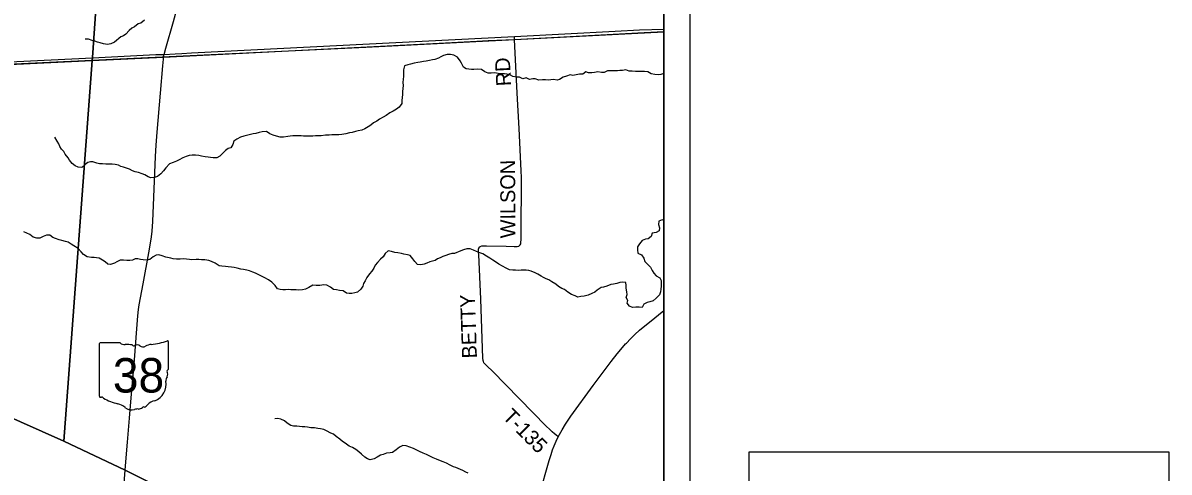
# Model space of a CAD drawing. Extents: x 0 to 36.5, y 0 to 25.3.
# Drawn here: x 6.451 to 10.831, y 15.88 to 17.597 of the extents above; entities that cross this region are included whole.
import ezdxf

# ---------------------------------------------------------------- set-up
doc = ezdxf.new("R2010")
doc.units = 0
for name, color, linetype in [('DV_X_Township_Line', 7, 'Continuous'), ('GM_X_Minor_River', 7, 'Continuous'), ('GM_X_Rail_Line', 7, 'Continuous'), ('GM_X_State_Location', 7, 'Continuous'), ('GM_X_State_Route', 7, 'Continuous'), ('GM_X_State_Shield', 7, 'Continuous'), ('GM_X_Township_Road', 7, 'Continuous'), ('GM_X_Township_Road_Text', 7, 'Continuous'), ('GM_X_US_Route', 7, 'Continuous'), ('SH_Cut_Line', 7, 'Continuous'), ('SH_Data', 7, 'Continuous'), ('SH_Text', 7, 'Continuous')]:
    doc.layers.add(name, color=color, linetype=linetype)

msp = doc.modelspace()

# ---------------------------------------------------------------- linework, layer by layer
at = {"layer": 'DV_X_Township_Line'}
msp.add_lwpolyline([(5.1383, 16.6527), (6.6079, 15.9978), (6.7158, 17.4536), (6.7165, 17.4645), (6.7464, 17.8914), (6.7478, 17.9113), (6.7968, 18.6079), (6.9145, 19.9406), (6.9868, 20.9), (6.1845, 20.9)], dxfattribs=at)
for points in [[(8.9, 14.8674), (8.9, 20.9), (6.9868, 20.9), (6.9145, 19.9406), (6.7968, 18.6079), (6.7478, 17.9113), (6.7464, 17.8914), (6.7165, 17.4645), (6.7158, 17.4536), (6.6079, 15.9978), (6.8419, 15.8878), (7.703, 15.458), (7.7552, 15.432), (7.7814, 15.4189), (7.8139, 15.4027), (8.0723, 15.2737), (8.5228, 15.0526)], [(2.1, 16.2788), (2.1, 14.1), (8.9, 14.1), (8.9, 14.8674), (8.5228, 15.0526), (8.0723, 15.2737), (7.8139, 15.4027), (7.7814, 15.4189), (7.7552, 15.432), (7.703, 15.458), (6.8419, 15.8878), (6.6079, 15.9978), (5.1383, 16.6527), (4.8891, 16.7511), (4.0938, 16.595), (2.4938, 16.3413), (2.1039, 16.2931)]]:
    msp.add_lwpolyline(points, close=True, dxfattribs=at)
at = {"layer": 'GM_X_Minor_River'}
for points in [[(6.9151, 17.6076), (6.9013, 17.5966), (6.8915, 17.5929), (6.877, 17.5815), (6.8671, 17.577), (6.8568, 17.5675), (6.845, 17.5546), (6.8355, 17.5478), (6.8252, 17.5444), (6.8016, 17.5239), (6.7872, 17.5167), (6.7738, 17.5141), (6.759, 17.5168), (6.7458, 17.5207), (6.7363, 17.5233), (6.7253, 17.5268), (6.7158, 17.5302), (6.7021, 17.5345), (6.6884, 17.5349)], [(8.9, 17.404), (8.8887, 17.4), (8.8781, 17.3989), (8.8655, 17.3994), (8.8522, 17.4026), (8.839, 17.4099), (8.8269, 17.4112), (8.8158, 17.4109), (8.8026, 17.411), (8.7919, 17.4115), (8.7794, 17.412), (8.7676, 17.4121), (8.7547, 17.4171), (8.7422, 17.4157), (8.7327, 17.4146), (8.7232, 17.414), (8.7099, 17.4133), (8.6977, 17.4134), (8.6852, 17.4139), (8.6718, 17.4076), (8.6623, 17.4077), (8.6483, 17.4101), (8.635, 17.4079), (8.6251, 17.4061), (8.6118, 17.4058), (8.6019, 17.4097), (8.5905, 17.4014), (8.5775, 17.4012), (8.565, 17.3983), (8.552, 17.3961), (8.5422, 17.3981), (8.5285, 17.3936), (8.5151, 17.3899), (8.5018, 17.3813), (8.4922, 17.378), (8.4786, 17.3804), (8.4683, 17.3801), (8.458, 17.3783), (8.4486, 17.3799), (8.4368, 17.3789), (8.4227, 17.3778), (8.4091, 17.3833), (8.3996, 17.3837), (8.387, 17.3808), (8.3745, 17.3874), (8.3608, 17.3837), (8.3487, 17.3891), (8.3366, 17.3892), (8.3237, 17.3916), (8.3138, 17.3967), (8.3006, 17.4006), (8.2911, 17.4029), (8.2763, 17.4027), (8.2668, 17.4039), (8.2539, 17.4059), (8.2402, 17.4053), (8.2288, 17.405), (8.2159, 17.4097), (8.2031, 17.4186), (8.1883, 17.4206), (8.1746, 17.4192), (8.1647, 17.4193), (8.1552, 17.4197), (8.1454, 17.4217), (8.1344, 17.4279), (8.1266, 17.4428), (8.1221, 17.4523), (8.112, 17.4657), (8.098, 17.4738), (8.0847, 17.4762), (8.0718, 17.4764), (8.0588, 17.4723), (8.0485, 17.4678), (8.039, 17.4618), (8.0256, 17.4574), (8.0157, 17.4556), (8.0043, 17.453), (7.9925, 17.4504), (7.9815, 17.449), (7.9697, 17.4476), (7.9602, 17.4462), (7.9457, 17.4433), (7.932, 17.4396), (7.9225, 17.4374), (7.9091, 17.4326), (7.9056, 17.4181), (7.9059, 17.4063), (7.9054, 17.3923), (7.9037, 17.3817), (7.9033, 17.3695), (7.9035, 17.3577), (7.9031, 17.3467)], [(7.9031, 17.3467), (7.9022, 17.3345), (7.9017, 17.3231), (7.8992, 17.3011), (7.8987, 17.2889), (7.8883, 17.2746), (7.8788, 17.2678), (7.8662, 17.26), (7.8532, 17.2529), (7.8398, 17.2435), (7.8272, 17.2367), (7.8138, 17.2296), (7.8035, 17.2221), (7.7909, 17.2154), (7.7802, 17.206), (7.7707, 17.2004), (7.7577, 17.1921), (7.7466, 17.1877), (7.7317, 17.184), (7.7218, 17.1814), (7.7097, 17.1785), (7.699, 17.1767), (7.6845, 17.173), (7.6697, 17.1708), (7.6587, 17.1698), (7.6458, 17.1692), (7.6317, 17.1693), (7.6214, 17.1686), (7.607, 17.168), (7.5903, 17.1658), (7.5804, 17.1652), (7.5693, 17.1649), (7.5591, 17.1646), (7.5439, 17.1647), (7.534, 17.1648), (7.5238, 17.1645), (7.5139, 17.165), (7.5021, 17.1655), (7.4926, 17.1652), (7.4823, 17.1649), (7.4728, 17.1638), (7.4629, 17.1624), (7.4466, 17.1603), (7.434, 17.1604), (7.42, 17.1647), (7.4071, 17.1675), (7.3947, 17.1733), (7.3814, 17.1821), (7.3651, 17.1804), (7.3544, 17.1782), (7.3411, 17.1749), (7.3312, 17.1731), (7.3202, 17.1709), (7.295, 17.1643), (7.2824, 17.1598), (7.2687, 17.1527), (7.2576, 17.1448), (7.2537, 17.1323), (7.2452, 17.1202), (7.2357, 17.1165), (7.2258, 17.1098), (7.2031, 17.0875), (7.1917, 17.0808), (7.178, 17.0813), (7.1682, 17.0829), (7.1587, 17.0845), (7.148, 17.0857), (7.1332, 17.0874), (7.1234, 17.0897), (7.1101, 17.0914), (7.0976, 17.0911), (7.0869, 17.0901), (7.0751, 17.0867), (7.0625, 17.0812), (7.0484, 17.0733), (7.0385, 17.0681), (7.0247, 17.0632), (7.011, 17.0588), (6.9976, 17.0433), (6.988, 17.0316), (6.9776, 17.0199), (6.9654, 17.0094), (6.9539, 17.0057), (6.9399, 17.0054), (6.9293, 17.0086), (6.9168, 17.0159), (6.9066, 17.0202), (6.8922, 17.0252), (6.8804, 17.0284), (6.8702, 17.0323), (6.8585, 17.0377), (6.8471, 17.0416), (6.8357, 17.0451), (6.8259, 17.0486), (6.8161, 17.0533), (6.8039, 17.0564), (6.7922, 17.0577), (6.7823, 17.0566), (6.7678, 17.0575), (6.7553, 17.0588), (6.7439, 17.0585)], [(6.7439, 17.0585), (6.7333, 17.0608), (6.7189, 17.0655), (6.7094, 17.0656), (6.6995, 17.0638), (6.6884, 17.0563), (6.6758, 17.0442), (6.6621, 17.0459), (6.6508, 17.0502), (6.6391, 17.0598), (6.6293, 17.072), (6.6237, 17.0819), (6.6124, 17.0957), (6.6072, 17.1053), (6.5989, 17.1149), (6.5922, 17.1252), (6.5884, 17.1347), (6.5821, 17.1454), (6.5727, 17.1607)], [(8.9, 16.8414), (8.8943, 16.8438), (8.8817, 16.8393), (8.8797, 16.826), (8.8834, 16.8142), (8.8818, 16.8028), (8.8703, 16.7961), (8.8555, 16.7928), (8.8516, 16.7803), (8.8405, 16.7713), (8.8302, 16.7702), (8.8168, 16.7658), (8.8072, 16.7526), (8.7999, 16.7416), (8.7994, 16.7291), (8.8012, 16.7173), (8.8148, 16.7107), (8.8235, 16.6977), (8.8279, 16.6855), (8.8381, 16.6755), (8.8494, 16.6632), (8.8557, 16.6503), (8.8617, 16.6407), (8.8715, 16.6304), (8.8847, 16.6223), (8.8895, 16.612), (8.8894, 16.5914), (8.8885, 16.5793), (8.8876, 16.569), (8.8841, 16.5573), (8.8715, 16.5452), (8.8596, 16.5343), (8.8463, 16.5306), (8.8364, 16.5288), (8.8238, 16.5225), (8.8176, 16.5092), (8.8062, 16.5101), (8.7933, 16.5106), (8.7811, 16.5088), (8.7694, 16.5142), (8.76, 16.5261), (8.7627, 16.5355), (8.756, 16.5481), (8.7603, 16.5591), (8.7585, 16.5687), (8.7563, 16.5831), (8.7564, 16.5938), (8.755, 16.6044), (8.7421, 16.606), (8.7326, 16.6046), (8.72, 16.6009), (8.7078, 16.5991), (8.6972, 16.5966), (8.6823, 16.5914), (8.6701, 16.5865), (8.6606, 16.5855), (8.6457, 16.575), (8.6361, 16.5678), (8.6247, 16.5626), (8.6106, 16.5567), (8.5953, 16.5526), (8.5835, 16.5508), (8.5714, 16.5494), (8.5608, 16.5533), (8.5471, 16.5595), (8.5328, 16.5684), (8.52, 16.5776), (8.5101, 16.5822), (8.498, 16.5892), (8.4875, 16.598), (8.4727, 16.6077), (8.461, 16.6146), (8.4508, 16.6193), (8.441, 16.6239), (8.4311, 16.6297), (8.4187, 16.6366), (8.4085, 16.6421), (8.3933, 16.6487), (8.3838, 16.651), (8.3744, 16.6526), (8.3641, 16.6523), (8.3546, 16.6517), (8.3443, 16.651), (8.3333, 16.6518), (8.3238, 16.6523), (8.3105, 16.6539), (8.2973, 16.6594), (8.2833, 16.6671), (8.2693, 16.6748), (8.2572, 16.6837), (8.2474, 16.6902), (8.2357, 16.6979), (8.2221, 16.7053), (8.2089, 16.7149), (8.1975, 16.7184), (8.1847, 16.7235), (8.1725, 16.7285), (8.16, 16.7332), (8.1475, 16.7333), (8.1349, 16.7296)], [(6.9968, 16.702), (6.9828, 16.7071), (6.9707, 16.7106), (6.9604, 16.7092), (6.9486, 16.7032), (6.9355, 16.6927), (6.9253, 16.6905), (6.9101, 16.6917), (6.9002, 16.6926), (6.8903, 16.695), (6.8797, 16.6954), (6.8698, 16.6906), (6.8599, 16.6888), (6.8481, 16.6892), (6.8356, 16.6905), (6.8223, 16.6899), (6.8101, 16.6839), (6.8005, 16.679), (6.7861, 16.6738), (6.7758, 16.6747), (6.7656, 16.6835), (6.7554, 16.6908), (6.7429, 16.6974), (6.7323, 16.699), (6.7228, 16.6998), (6.7126, 16.7003), (6.697, 16.7031), (6.683, 16.7116), (6.6733, 16.7227), (6.662, 16.7353), (6.6461, 16.7446), (6.6355, 16.7515), (6.6246, 16.7588), (6.614, 16.7616), (6.5992, 16.7651), (6.5897, 16.7679), (6.5753, 16.7726), (6.5651, 16.7768), (6.5538, 16.7853), (6.5412, 16.7854), (6.5287, 16.781), (6.5153, 16.7746), (6.5047, 16.7743), (6.4906, 16.7775), (6.4778, 16.7879), (6.4657, 16.7933), (6.454, 16.798)], [(8.1349, 16.7296), (8.1243, 16.7263), (8.1002, 16.7159), (8.0896, 16.7152), (8.0774, 16.7115), (8.0667, 16.7078), (8.0561, 16.7037), (8.0461, 16.6989), (8.0358, 16.6948), (8.0263, 16.6895), (8.0168, 16.6866), (8.0065, 16.6836), (7.9947, 16.6788), (7.9848, 16.6751), (7.9722, 16.6725), (7.9593, 16.6742), (7.9488, 16.6853), (7.9405, 16.6956), (7.9311, 16.7075), (7.9209, 16.711), (7.9072, 16.7134), (7.8977, 16.7154), (7.8841, 16.7185), (7.8727, 16.7198), (7.8594, 16.7229), (7.8473, 16.7253), (7.8354, 16.7155), (7.8273, 16.7035), (7.817, 16.694), (7.8062, 16.6816), (7.7974, 16.6707), (7.7916, 16.6601), (7.7847, 16.6487), (7.7755, 16.6374), (7.7658, 16.6238), (7.7585, 16.6106), (7.7527, 16.6007), (7.7496, 16.5913), (7.7423, 16.5788), (7.7296, 16.5683), (7.719, 16.5649), (7.7075, 16.5631), (7.6973, 16.5632), (7.6874, 16.5644), (7.675, 16.5725), (7.6613, 16.5749), (7.6488, 16.5762), (7.6382, 16.5786), (7.6261, 16.5874), (7.6125, 16.5951), (7.6007, 16.5964), (7.5855, 16.5935), (7.5718, 16.5936), (7.5585, 16.5948), (7.5436, 16.5859), (7.5306, 16.5799), (7.5192, 16.5762), (7.5059, 16.5759), (7.4953, 16.5768), (7.485, 16.5772), (7.4744, 16.5773), (7.4641, 16.5778), (7.4543, 16.5771), (7.444, 16.5769), (7.4337, 16.5777), (7.4239, 16.5804), (7.4153, 16.5931), (7.4021, 16.6057), (7.3896, 16.6153), (7.3756, 16.6227), (7.3628, 16.6296), (7.3499, 16.6358), (7.3397, 16.6401), (7.3291, 16.6448), (7.317, 16.6498), (7.3068, 16.6522), (7.2946, 16.6549), (7.2836, 16.6562), (7.2696, 16.6601), (7.2586, 16.6617), (7.248, 16.6637), (7.2351, 16.6653), (7.2256, 16.6658), (7.2111, 16.6674), (7.2013, 16.6691), (7.1862, 16.6783), (7.1722, 16.6849), (7.1619, 16.6892), (7.1464, 16.6912), (7.1335, 16.6913), (7.1236, 16.6922), (7.1126, 16.6923), (7.097, 16.692), (7.0875, 16.6929), (7.0761, 16.6941), (7.0655, 16.6949), (7.0514, 16.6943), (7.0378, 16.6941), (7.0252, 16.6949), (7.0158, 16.698), (6.9968, 16.702)], [(7.6981, 15.9795), (7.6823, 15.9903), (7.6725, 15.9968), (7.6627, 16.006), (7.6487, 16.016), (7.6374, 16.0252), (7.6272, 16.0295), (7.6117, 16.0384), (7.6007, 16.0431), (7.5886, 16.0454), (7.5783, 16.0471), (7.5654, 16.0491), (7.5514, 16.0496), (7.5385, 16.0516), (7.5278, 16.0528), (7.5183, 16.0537), (7.5085, 16.0545), (7.4982, 16.0554), (7.4857, 16.0562), (7.4751, 16.0586), (7.4607, 16.0675), (7.4505, 16.0759), (7.4373, 16.0825), (7.4255, 16.0845), (7.4138, 16.0842)], [(8.1531, 15.8759), (8.1433, 15.8805), (8.1316, 15.8867), (8.1058, 15.8976), (8.096, 15.9007), (8.0831, 15.9069), (8.0695, 15.9146), (8.0566, 15.9193), (8.0464, 15.9228), (8.0317, 15.9298), (8.0184, 15.9352), (8.0059, 15.941), (7.9934, 15.9472), (7.9802, 15.9527), (7.9666, 15.9585), (7.9533, 15.9654), (7.9431, 15.9705), (7.9295, 15.9759), (7.9159, 15.9806), (7.9026, 15.9822), (7.8896, 15.9759), (7.877, 15.965), (7.8636, 15.9552), (7.8541, 15.9542), (7.8408, 15.9531), (7.8274, 15.9479), (7.8179, 15.945), (7.8049, 15.9375), (7.7927, 15.9312), (7.7775, 15.9275), (7.768, 15.9306), (7.7578, 15.9368), (7.745, 15.9487), (7.7348, 15.9579), (7.7235, 15.9667), (7.7099, 15.9737), (7.6981, 15.9795)]]:
    msp.add_lwpolyline(points, dxfattribs=at)
at = {"layer": 'GM_X_Rail_Line'}
msp.add_lwpolyline([(4.8132, 17.3633), (5.4924, 17.3965), (6.4721, 17.4436), (7.7613, 17.5038), (8.9, 17.5625)], dxfattribs=at)
at = {"layer": 'GM_X_State_Route'}
for points in [[(6.9887, 17.4664), (6.9907, 17.4765), (6.9969, 17.5008), (7.0261, 17.6023), (7.0395, 17.6501), (7.0479, 17.6787)], [(6.9318, 16.7185), (6.9412, 16.7706), (6.9441, 16.789), (6.9453, 16.8014), (6.9475, 16.8386), (6.9576, 17.0869), (6.96, 17.1301), (6.9638, 17.1798), (6.9765, 17.3284), (6.9859, 17.4336), (6.9878, 17.4584), (6.9887, 17.4664)], [(6.8647, 16.1643), (6.8694, 16.2208), (6.8772, 16.3097), (6.8861, 16.4274), (6.8904, 16.4769), (6.893, 16.5016), (6.8959, 16.52), (6.9101, 16.5995), (6.9318, 16.7185)], [(6.8421, 15.8872), (6.8474, 15.9506), (6.8507, 15.994), (6.8586, 16.0868), (6.8647, 16.1643)], [(6.8414, 15.6403), (6.8345, 15.6594), (6.8308, 15.6721), (6.8295, 15.6781), (6.8285, 15.6843), (6.8276, 15.6973), (6.8277, 15.7029), (6.8304, 15.7401), (6.8366, 15.8206), (6.8421, 15.8872)]]:
    msp.add_lwpolyline(points, dxfattribs=at)
at = {"layer": 'GM_X_State_Shield'}
for p, q in [((6.7431, 16.3703), (6.7431, 16.1702)), ((6.8229, 16.3738), (6.7457, 16.3738)), ((7.0068, 16.274), (7.0068, 16.3787)), ((7.0068, 16.2741), (7.0068, 16.274))]:
    msp.add_line(p, q, dxfattribs=at)
for centre, radius, start, end in [((6.9129, 16.6466), 0.2796, 275.8445, 288.9065), ((7.0039, 16.3792), 0.00294, 351.8621, 97.738), ((6.7461, 16.3707), 0.00305, 98.1301, 188.1301), ((6.8413, 16.397), 0.0296, 231.6195, 271.1119), ((6.8511, 16.2614), 0.1064, 80.4867, 94.9883), ((6.8753, 16.3718), 0.00855, 219.7921, 297.1024), ((6.8878, 16.3486), 0.0178, 54.4667, 119.1411), ((6.9108, 16.3804), 0.0214, 233.8562, 294.8282), ((6.9485, 16.3126), 0.0563, 97.3462, 120.7689), ((7.0061, 16.2663), 0.00454, 107.944, 210.337), ((6.9772, 16.2531), 0.0273, 340.033, 23.6496), ((7.0037, 16.2736), 0.00314, 289.6038, 7.7341), ((6.9285, 16.2169), 0.0699, 292.3089, 8.9858), ((7.0173, 16.2302), 0.0198, 136.8065, 186.9296), ((6.7462, 16.1698), 0.00308, 171.9584, 258.3066), ((6.7466, 16.1902), 0.0235, 267.339, 280.6039), ((6.7514, 16.1587), 0.00848, 29.7484, 93.2717), ((6.8585, 16.3385), 0.2019, 240.4129, 257.1985), ((6.7983, 16.0803), 0.0632, 47.1842, 75.836), ((6.8666, 16.1577), 0.0401, 230.7004, 286.2918), ((6.8898, 16.0885), 0.0329, 85.6951, 111.2099), ((6.8927, 16.1427), 0.0214, 268.777, 315.5493), ((6.9121, 16.1233), 0.00601, 65.7517, 132.6484), ((6.9095, 16.1508), 0.0226, 282.8732, 323.2771), ((6.958, 16.114), 0.0383, 94.4031, 142.5768)]:
    msp.add_arc(centre, radius, start, end, dxfattribs=at)
at = {"layer": 'GM_X_Township_Road'}
msp.add_line((8.33, 17.5341), (8.33, 17.5451), dxfattribs=at)
for points in [[(8.192, 16.7303), (8.1923, 16.7323), (8.1941, 16.7382), (8.195, 16.7393), (8.1987, 16.7423), (8.2045, 16.7446), (8.2106, 16.7448), (8.2168, 16.7445), (8.223, 16.7448), (8.2973, 16.7431), (8.3281, 16.742), (8.3392, 16.7423), (8.3464, 16.7442), (8.348, 16.7452), (8.351, 16.7483), (8.3534, 16.7527), (8.3537, 16.7538), (8.3544, 16.76), (8.3545, 16.7662), (8.3551, 16.7723), (8.3548, 16.7909), (8.3549, 16.8466), (8.3557, 16.9456), (8.3557, 17.0068), (8.3551, 17.0323), (8.3471, 17.1931), (8.34, 17.3291), (8.33, 17.5341)], [(8.2112, 16.3027), (8.2098, 16.3071), (8.2086, 16.3162), (8.2006, 16.5408), (8.1928, 16.712), (8.1916, 16.72), (8.1914, 16.7262), (8.192, 16.7303)], [(8.4965, 16.0151), (8.487, 16.022), (8.4822, 16.0259), (8.4729, 16.0341), (8.464, 16.0428), (8.4511, 16.0561), (8.2449, 16.2655), (8.2245, 16.2855), (8.219, 16.2913), (8.213, 16.2984), (8.2112, 16.3027)]]:
    msp.add_lwpolyline(points, dxfattribs=at)
at = {"layer": 'GM_X_US_Route'}
for points in [[(6.7161, 17.4531), (6.9887, 17.4664), (7.9931, 17.517), (8.1854, 17.5267), (8.2288, 17.5292), (8.33, 17.5341), (8.8248, 17.5602), (8.9, 17.5643)], [(6.7167, 17.464), (6.9588, 17.4758), (6.9907, 17.4765), (7.0333, 17.4785), (7.058, 17.4807), (7.0952, 17.4827), (8.33, 17.5451), (8.714, 17.5655), (8.807, 17.57), (8.9, 17.5731)], [(5.1992, 17.3544), (5.2169, 17.3614), (5.2446, 17.3708), (5.2826, 17.3799), (5.3257, 17.3854), (5.8207, 17.4095), (6.7161, 17.4531)], [(5.2027, 17.3625), (5.2321, 17.3745), (5.2604, 17.3838), (5.2906, 17.3909), (5.3234, 17.3959), (5.3708, 17.3992), (5.8211, 17.4202), (6.7167, 17.464)], [(8.757, 16.3733), (8.7725, 16.3895), (8.789, 16.4055), (8.8073, 16.4221), (8.8214, 16.4341), (8.8452, 16.4536), (8.9, 16.4981)], [(8.4965, 16.0151), (8.5116, 16.0417), (8.5242, 16.0631), (8.5343, 16.0788), (8.5449, 16.0941), (8.6307, 16.211), (8.6993, 16.3034), (8.7219, 16.3328), (8.7418, 16.3565), (8.7542, 16.3704), (8.757, 16.3733)], [(8.2879, 15.5553), (8.3251, 15.6039), (8.3402, 15.624), (8.3505, 15.6382), (8.3603, 15.6529), (8.3715, 15.6709), (8.3805, 15.6869), (8.3889, 15.7032), (8.3969, 15.7198), (8.4044, 15.7365), (8.409, 15.7479), (8.4143, 15.7622), (8.4247, 15.7943), (8.4619, 15.9239), (8.4691, 15.9474), (8.4752, 15.9648), (8.4813, 15.9806), (8.4891, 15.999), (8.4965, 16.0151)]]:
    msp.add_lwpolyline(points, dxfattribs=at)
at = {"layer": 'SH_Cut_Line'}
msp.add_lwpolyline([(4.4591, 20.9), (3.3366, 20.9), (3.2612, 20.6041), (2.8463, 19.037), (2.6265, 18.2595), (2.5271, 17.8912), (2.5226, 17.8751), (2.5165, 17.8524), (2.5144, 17.8445), (2.4192, 17.4891), (2.3437, 17.2326), (2.3403, 17.2198), (2.1039, 16.2931), (2.1, 16.2788), (2.1, 14.1), (8.9, 14.1), (8.9, 20.9), (6.1845, 20.9)], dxfattribs=at)
at = {"layer": 'SH_Data'}
for p, q in [((9, 21), (9, 14)), ((8.9, 20.9), (8.9, 14.1))]:
    msp.add_line(p, q, dxfattribs=at)
at = {"layer": 'SH_Text'}
msp.add_lwpolyline([(10.8308, 15.9562), (9.2246, 15.9562), (9.2246, 15.2045), (10.8308, 15.2045)], close=True, dxfattribs=at)

# ---------------------------------------------------------------- texts
at = {"layer": 'GM_X_State_Location'}
for s in ['s', 'r']:
    msp.add_text(s, height=0.000189, dxfattribs=at).set_placement((6.872, 16.257))
msp.add_text('38', height=0.000189, rotation=0, dxfattribs=at).set_placement((6.8243, 16.2432))
at = {"layer": 'GM_X_State_Shield'}
msp.add_text('38', height=0.13184, dxfattribs=at).set_placement((6.7948, 16.1843))
at = {"layer": 'GM_X_Township_Road_Text'}
for s, rotation, p in [('RD', 92.9593, (8.317, 17.3567)), ('WILSON', 90.1659, (8.3328, 16.7739)), ('BETTY', 91.8621, (8.1861, 16.3155)), ('T-135', 314.6086, (8.2807, 16.0887))]:
    msp.add_text(s, height=0.05682, rotation=rotation, dxfattribs=at).set_placement(p)

doc.saveas('drawing.dxf')
